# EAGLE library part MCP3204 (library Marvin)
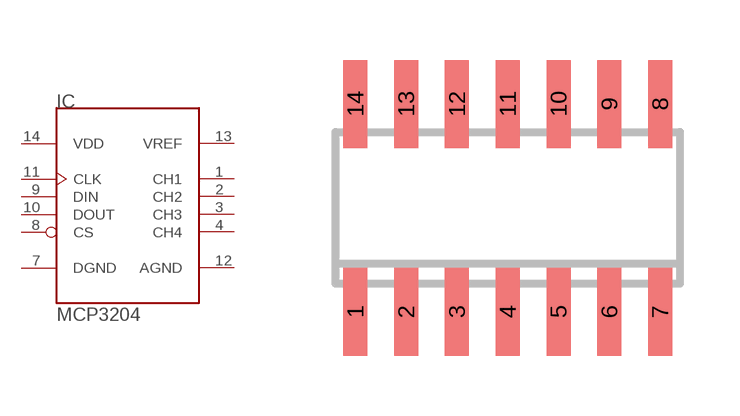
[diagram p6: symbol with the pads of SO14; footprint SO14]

Designator prefix IC

## MCP3204S  [SO14]
1  CH1
2  CH2
3  CH3
4  CH4
7  DGND
8  CS
9  DIN
10  DOUT
11  CLK
12  AGND
13  VREF
14  VDD

## Footprint SO14 (pad centres in mm)
smd 0.6 x 2.2: 1 -3.81,-2.6; 2 -2.54,-2.6; 3 -1.27,-2.6; 4 0,-2.6; 5 1.27,-2.6; 6 2.54,-2.6; 7 3.81,-2.6; 8 3.81,2.6; 9 2.54,2.6; 10 1.27,2.6; 11 0,2.6; 12 -1.27,2.6; 13 -2.54,2.6; 14 -3.81,2.6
